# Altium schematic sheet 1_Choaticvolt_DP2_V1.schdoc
size 309 x 223 mm; Symbol: Sheet-Symbol_A4; Device: Sheet-Symbol_A4; @Project Name: Chaoticvolt-SensorHUB-v1.0; @Page Count: 1; @Update Date: 2024-12-07; @Create Date: 2024-12-06; @Schematic Name: Choaticvolt_DP2_V1; @Page No: 1; @Page Name: Choaticvolt_DP2_V1; Company: Chaoticvolt; Reviewed: Robin; Version: V1.0; Page Size: A4; Part Number: CV-SHV1; Drawn: Robin; Title Block Position: 3; Width: 1170; Height: 825; Region Start: 1; X Region Count: 6; Y Region Count: 4; Blade Width: 10; @Board Name: Choaticvolt_DP2_V1; @Create Time: 10:28:50; @Update Time: 20:36:33
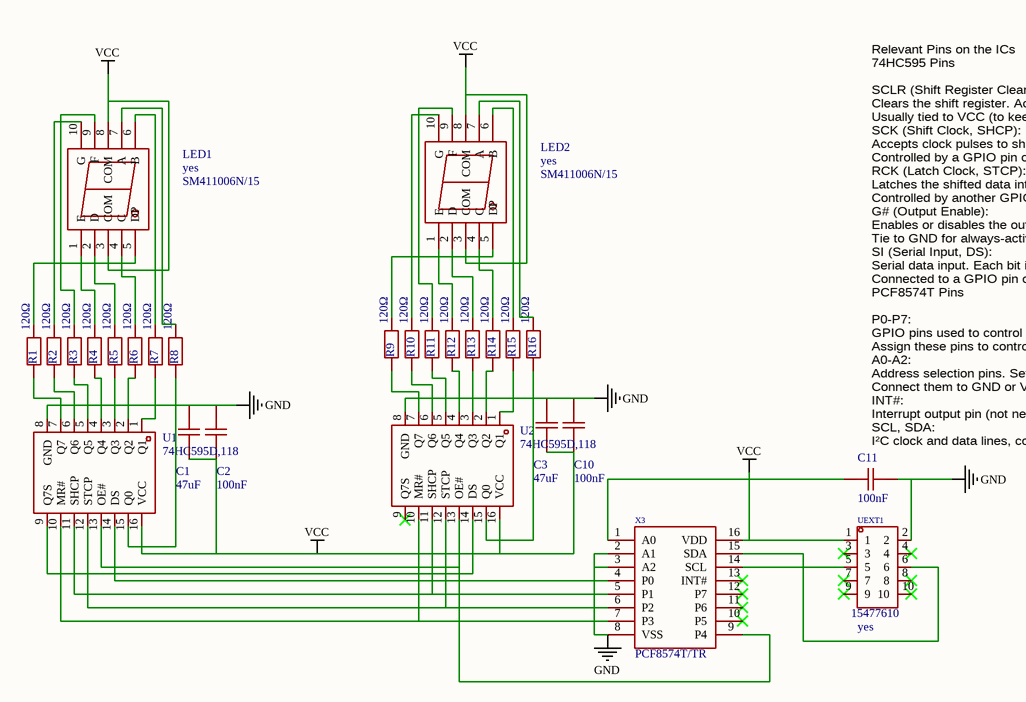
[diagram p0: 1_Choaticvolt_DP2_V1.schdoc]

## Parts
C1  47uF  [C1206]  (value not drawn)
C2  100nF  [C0402]  (value not drawn)
C3  47uF  [C1206]  (value not drawn)
C10  100nF  [C0402]  (value not drawn)
C11  100nF  [C0402]  (value not drawn)
LED1  Add into BOM: yes  [LED-SEG-TH_10P-L24.0-W34.0-P2.54-S30.48-BL]  (hidden comment: SM411006N/15)
LED2  Add into BOM: yes  [LED-SEG-TH_10P-L24.0-W34.0-P2.54-S30.48-BL]  (hidden comment: SM411006N/15)
R1  120Ω  [R0805]  (value not drawn)
R2  120Ω  [R0805]  (value not drawn)
R3  120Ω  [R0805]  (value not drawn)
R4  120Ω  [R0805]  (value not drawn)
R5  120Ω  [R0805]  (value not drawn)
R6  120Ω  [R0805]  (value not drawn)
R7  120Ω  [R0805]  (value not drawn)
R8  120Ω  [R0805]  (value not drawn)
R9  120Ω  [R0805]  (value not drawn)
R10  120Ω  [R0805]  (value not drawn)
R11  120Ω  [R0805]  (value not drawn)
R12  120Ω  [R0805]  (value not drawn)
R13  120Ω  [R0805]  (value not drawn)
R14  120Ω  [R0805]  (value not drawn)
R15  120Ω  [R0805]  (value not drawn)
R16  120Ω  [R0805]  (value not drawn)
U1  74HC595D,118  [SOIC-16_L9.9-W3.9-P1.27-LS6.0-BL]  (value not drawn)
U2  74HC595D,118  [SOIC-16_L9.9-W3.9-P1.27-LS6.0-BL]  (value not drawn)
UEXT1  Add into BOM: yes  [IDC-TH_15477610]  (hidden comment: 15477610)
X3  PCF8574T/TR  [SO-16_L10.3-W7.5-P1.27-LS10.3-BL]  (value not drawn)

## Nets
GND: C1.2 C2.2 C3.2 C10.2 C11.1 U1.8(GND) U2.8(GND) UEXT1.2 X3.2(A1) X3.3(A2) X3.8(VSS)
VCC: C1.1 C2.1 C3.1 C10.1 C11.2 LED1.3(COM) LED1.8(COM) LED2.3(COM) LED2.8(COM) U1.16(VCC) U2.16(VCC) UEXT1.1 X3.1(A0) X3.16(VDD)
NetLED1_1: LED1.1(E) R4.1
NetLED1_2: LED1.2(D) R5.1
NetLED1_4: LED1.4(C) R6.1
NetLED1_5: LED1.5(DP) R1.1
NetLED1_6: LED1.6(B) R7.1
NetLED1_7: LED1.7(A) R8.1
NetLED1_9: LED1.9(F) R3.1
NetLED1_10: LED1.10(G) R2.1
NetLED2_1: LED2.1(E) R12.1
NetLED2_2: LED2.2(D) R13.1
NetLED2_4: LED2.4(C) R14.1
NetLED2_5: LED2.5(DP) R9.1
NetLED2_6: LED2.6(B) R15.1
NetLED2_7: LED2.7(A) R16.1
NetLED2_9: LED2.9(F) R11.1
NetLED2_10: LED2.10(G) R10.1
NetR1_2: R1.2 U1.7(Q7)
NetR2_2: R2.2 U1.6(Q6)
NetR3_2: R3.2 U1.5(Q5)
NetR4_2: R4.2 U1.4(Q4)
NetR5_2: R5.2 U1.3(Q3)
NetR6_2: R6.2 U1.2(Q2)
NetR7_2: R7.2 U1.1(Q1)
NetR8_2: R8.2 U1.15(Q0)
NetR9_2: R9.2 U2.7(Q7)
NetR10_2: R10.2 U2.6(Q6)
NetR11_2: R11.2 U2.5(Q5)
NetR12_2: R12.2 U2.4(Q4)
NetR13_2: R13.2 U2.3(Q3)
NetR14_2: R14.2 U2.2(Q2)
NetR15_2: R15.2 U2.1(Q1)
NetR16_2: R16.2 U2.15(Q0)
NetU1_9: U1.9(Q7S) U2.14(DS)
NetU1_10: U1.10(MR#) U2.10(MR#) X3.7(P3)
NetU1_11: U1.11(SHCP) U1.13(OE#) U2.11(SHCP) U2.13(OE#) X3.5(P1) X3.9(P4)
NetU1_12: U1.12(STCP) U2.12(STCP) X3.6(P2)
NetU1_14: U1.14(DS) X3.4(P0)
NetUEXT1_5: UEXT1.5 X3.14(SCL)
NetUEXT1_6: UEXT1.6 X3.15(SDA)

Not connected (* = marked no-connect by the designer): U2 9(Q7S)*; UEXT1 3* 4* 7* 8* 9* 10*; X3 10(P5)* 11(P6)* 12(P7)* 13(INT#)*

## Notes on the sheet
- Relevant Pins on the ICs
  74HC595 Pins
  SCLR (Shift Register Clear):
  Clears the shift register. Active low.
  Usually tied to VCC (to keep the register active), unless you need to reset it dynamically.
  SCK (Shift Clock, SHCP):
  Accepts clock pulses to shift bits into the register.
  Controlled by a GPIO pin on the PCF8574T.
  RCK (Latch Clock, STCP):
  Latches the shifted data into the output register.
  Controlled by another GPIO pin on the PCF8574T.
  G# (Output Enable):
  Enables or disables the outputs. Active low.
  Tie to GND for always-active outputs unless you need to dynamically enable/disable them.
  SI (Serial Input, DS):
  Serial data input. Each bit is shifted into the register via this pin.
  Connected to a GPIO pin on the PCF8574T.
  PCF8574T Pins
  P0-P7:
  GPIO pins used to control the 74HC595.
  Assign these pins to control the 74HC595's SCK, RCK, and SI.
  A0-A2:
  Address selection pins. Set these to define the I²C address of the PCF8574T.
  Connect them to GND or VCC as needed.
  INT#:
  Interrupt output pin (not needed in this application; leave unconnected).
  SCL, SDA:
  I²C clock and data lines, connected to your microcontroller.

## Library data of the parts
C1 C3 = CL31A476MPHNNNE: Capacitance: Tolerance:±20% Tolerance:±20% Voltage Rated: Temperature Coefficient:; Manufacturer: SAMSUNG(三星); Add into BOM: yes; Tolerance: ±20%; Check: false
C2 C10 C11 = CL05B104KO5NNNC: Capacitance: Tolerance:±10% Tolerance:±10% Voltage Rated: Temperature Coefficient:; Manufacturer: SAMSUNG(三星); Symbol: C1210C104K1RAC7800; Add into BOM: yes; Tolerance: ±10%; Check: false
LED1 LED2 = SM411006N/15: Number of Characters:1Bit Luminous Color:Red LED Polarity:共阳极 Digit/Alpha Size(inch):1; Manufacturer: ARKLED(方舟); Number of Characters: 1Bit; Luminous Color: Red; LED Polarity: 共阳极; Digit/Alpha Size(inch): 1; Check: false
R1-R16 = 0805W8F1200T5E: Type:Thick Film Resistors Resistance: Tolerance:±1% Tolerance:±1% Power(Watts): Overload Voltage (Max): Temperature Coefficient:±100ppm/℃ Temperature Coefficient:±100ppm/℃ Operating Temperature Range:-55℃~+155℃ Operating Temperature Range:-55℃~+155℃; Manufacturer: UNI-ROYAL(厚声); Symbol: RK73H2ETTD2700F; Add into BOM: yes; Tolerance: ±1%; Check: false
U1 U2 = 74HC595D,118: Function:Serial to serial or parallel Supply Voltage:2V~6V Supply Voltage:2V~6V Number of Elements:1 Number of Bits per Element:8 Output Type:Tri-State Series: Operating Temperature:-40℃~+125℃ Operating Temperature:-40℃~+125℃; Manufacturer: Nexperia(安世); Add into BOM: yes; Supply Voltage: 2V~6V; Number of Elements: 1; Number of Bits per Element: 8; Check: false
UEXT1 = 15477610: Pins Structure:2x5P Pitch:2.54mm Mounting Style:- Reference Series:- Number of Pins:10P Number of Rows:2 Number of PINs Per Row:5 Row Spacing:2.54mm Contact Material:Copper Alloy; Manufacturer: MOLEX; Pins Structure: 2x5P; Pitch: 2.54mm; Number of PINs Per Row: 5; Check: false
X3 = PCF8574T/TR: Interface:I2C Number of I/O:8; Manufacturer: HGSEMI(华冠); Symbol: PCF8574T/3,518; Add into BOM: yes; Interface: I2C; Number of I/O: 8; Check: false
